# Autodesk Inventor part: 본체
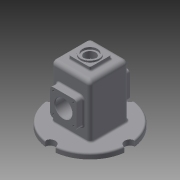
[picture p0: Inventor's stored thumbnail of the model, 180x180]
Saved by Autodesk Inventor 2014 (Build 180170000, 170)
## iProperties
Created: 2018-07
Part Number: 본체
Material: Generic
Document SubType Name: Modeling
Designer: kh
Density: 1 g/cm^3
Appearance: Default
Author: kh
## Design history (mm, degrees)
sketch "Sketch1"
  geometry: C1 r 75 at (0, 0); 1 further point
  constraints: 1 centre point, 1 coincident
  dimensions: "d0" = 150 diameter of C1
extrude "Extrusion1" new body sketch "Sketch1" distance "d1" = 10; taper "d2" = 0 deg
sketch "Sketch2"
  geometry: L1 (-37, 37)-(37, 37); L2 (37, 37)-(37, -37); L3 (37, -37)-(-37, -37); L4 (-37, -37)-(-37, 37); L5 (-37, 37)-(37, -37); L6 (37, 37)-(-37, -37); 1 further point
  constraints: 12 end point, 2 midpoint, 2 parallel, 1 horizontal, 1 perpendicular
  dimensions: "d3" = 74 distance of L2.end L3.end; "d4" = 74 distance of L1.end L2.end
extrude "Extrusion2" join sketch "Sketch2" distance "d5" = 100; taper "d6" = 0 deg
sketch "Sketch3"
  geometry: L1 (-20, 20)-(20, 20); L2 (20, 20)-(20, -20); L3 (20, -20)-(-20, -20); L4 (-20, -20)-(-20, 20); L5 (-20, 20)-(20, -20); L6 (20, 20)-(-20, -20); 1 further point
  constraints: 12 end point, 2 midpoint, 2 parallel, 1 horizontal, 1 perpendicular
  dimensions: "d7" = 40 distance of L2.end L3.end; "d8" = 40 distance of L1.end L2.end
extrude "Extrusion3" join sketch "Sketch3" distance "d9" = 7; taper "d10" = 0 deg
sketch "Sketch4"
  geometry: C1 r 17.5 at (0, 0); 1 further point
  constraints: 1 centre point, 1 coincident
  dimensions: "d11" = 35 diameter of C1
extrude "Extrusion4" join sketch "Sketch4" distance "d12" = 3; taper "d13" = 0 deg
node "Sketch5"
sketch "Sketch6"
  geometry: L1 (-25, 80)-(25, 80); L2 (25, 80)-(25, 30); L3 (25, 30)-(-25, 30); L4 (-25, 30)-(-25, 80); L5 (-25, 80)-(25, 30); L6 (25, 80)-(-25, 30); L7 (0, 0)-(0, 13.145); 2 further points
  constraints: 14 end point, 3 midpoint, 3 parallel, 1 horizontal, 1 perpendicular, 1 point on line
  dimensions: "d25" = 50 distance of L2.end L3.end; "d26" = 50 distance of L1.end L2.end; "d27" = 55 distance of point (0, 55) L7.start
extrude "Extrusion6" join sketch "Sketch6" stored distance "d28" = 100; taper "d29" = 0 deg
sketch "Sketch7"
  geometry: L1 (37, 110)-(-37, 110) reference; L2 (0, 110)-(0, 73.332); L3 (-50, 80)-(-50, 30) reference; L4 (-50, 55)-(100, 55); L5 (32, 30)-(32, 0); L6 (32, 0)-(-32, 0); L7 (-32, 0)-(-32, 30); L8 (32, 105)-(-32, 105); L9 (-32, 105)-(-32, 80); L10 (-37, 10)-(-37, 110) reference; L11 (37, 10)-(37, 110) reference; L12 (-75, 0)-(75, 0) reference; L13 (-32, 80)-(-25, 77.452); L14 (-25, 77.452)-(-25, 32.548); L15 (-25, 32.548)-(-32, 30); L16 (-32, 0)-(32, 0); L17 (32, 105)-(32, 80); L18 (32, 80)-(25, 77.452); L19 (25, 77.452)-(25, 32.548); L20 (25, 32.548)-(32, 30); 4 further points
  constraints: 30 end point, 7 midpoint, 4 perpendicular, 2 parallel, 1 collinear, 1 point on line
  dimensions: "d31" = 5 distance between parallel lines of L10 L7; "d32" = 5 distance between parallel lines of L10 L9; "d33" = 5 distance between parallel lines of L1 L8; "d35" = 5 distance between parallel lines of L11 L5; "d84" = 110 deg angle of L9 L13; "d85" = 110 deg angle of L7 L15; "d86" = 7 distance from line of L9 L13.end; "d87" = 50 distance of L7.end L9.end; "d88" = 7 horizontal distance of L19.end L5.start; "d89" = 5 distance between parallel lines of L17 L11; "d91" = 110 deg angle of L18 L17; "d92" = 110 deg angle of L5 L20; "d106" = 50 distance of L5.start L17.end
sketch "Sketch8"
  geometry: L1 (25, 80)-(-25, 80) reference; L2 (-25, 80)-(-25, 30) reference; L3 (-25, 30)-(25, 30) reference; L4 (25, 30)-(25, 80) reference; L5 (-25, 80)-(25, 30); C1 r 16 at (0, 55); 2 further points
  constraints: 2 end point, 1 centre point, 1 coincident, 1 midpoint
  dimensions: "d51" = 32 diameter of C1
extrude "Extrusion8" cut sketch "Sketch8" stored distance "d52" = 64; taper "d53" = 0 deg
sketch "Sketch9"
  geometry: L1 (37, 37)-(37, -37) reference; L2 (37, -37)-(-37, -37) reference; L3 (-37, -37)-(-37, 37) reference; L4 (-37, 37)-(37, 37) reference; L5 (0, 0)-(0, 75); C1 r 10 at (0, 75); 2 further points
  constraints: 2 coincident, 2 end point, 1 centre point, 1 perpendicular, 1 vertical alignment, 1 other
  dimensions: "d54" = 20 diameter of C1
extrude "Extrusion9" cut sketch "Sketch9" stored distance "d55" = 64; taper "d56" = 0 deg
pattern_circular "Circular Pattern1" dims angle "d58" = 360 deg
fillet "Fillet1" dims "d60" = 6, "d61" = 8, "d62" = 3
sketch "Sketch10"
  geometry: L1 (-19, -80)-(19, -80) reference; L2 (25, -74)-(25, -36) reference; L3 (19, -30)-(-19, -30) reference; L4 (-25, -36)-(-25, -74) reference; C1 r 16 at (0, -55) reference; A1 r 6 centre (-19, -74) between (-25, -74) and (-19, -80) reference; A2 r 6 centre (19, -74) between (19, -80) and (25, -74) reference; A3 r 6 centre (19, -36) between (25, -36) and (19, -30) reference; A4 r 6 centre (-19, -36) between (-19, -30) and (-25, -36) reference; 1 further point
hole "Hole2" sketch "Sketch10" at (19, -74), (-19, -74), (-19, -36), (19, -36) diameter "d63" = 3.459; stored, may be unused: countersink angle "d67" = 82 deg, drill point angle "d69" = 118 deg; dims "d64" = 8, "d65" = 3.023, "d66" = 4, "d68" = 10
mirror "Mirror1"
fillet "Fillet2" dims "d70" = 8, "d71" = 3
chamfer "Chamfer1" distance "d72" = 1; stored, may be unused: second distance "d73" = 2, angle "d74" = 45 deg
sketch "Sketch12"
  geometry: L1 (49.172, -82.523)-(4.828, -82.523); L2 (4.828, -82.523)-(4.828, -71.477); L3 (4.828, -71.477)-(49.172, -71.477); L4 (49.172, -71.477)-(49.172, -82.523); L5 (49.172, -82.523)-(4.828, -71.477); L6 (-8, 0)-(-8, -89) reference; L7 (11.5, -107)-(46.5, -107) reference; 2 further points
  constraints: 2 end point, 1 midpoint, 2 other
  dimensions: "d79" = 35 distance from line of L6 point (27, -77); "d80" = 30 distance from line of L7 point (27, -77)
emboss "Emboss2" sketch "Sketch12" dims "d81" = 0.5, "d82" = 0
extrude "Extrusion10" cut sketch "Sketch7" stored distance "d93" = 64; taper "d94" = 0 deg
fillet "Fillet3" dims "d95" = 3
fillet "Fillet4" dims "d96" = 3
hole "Hole3" diameter "d99" = 21; stored, may be unused: countersink angle "d103" = 90 deg, drill point angle "d105" = 118 deg; dims "d97" = 10, "d98" = 10, "d100" = 6, "d101" = 28, "d102" = 4, "d104" = 8
body "Solid1"
node "Projected Loop1"
node "Projected Loop2"
node "Projected Loop3"
